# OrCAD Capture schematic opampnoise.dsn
size A
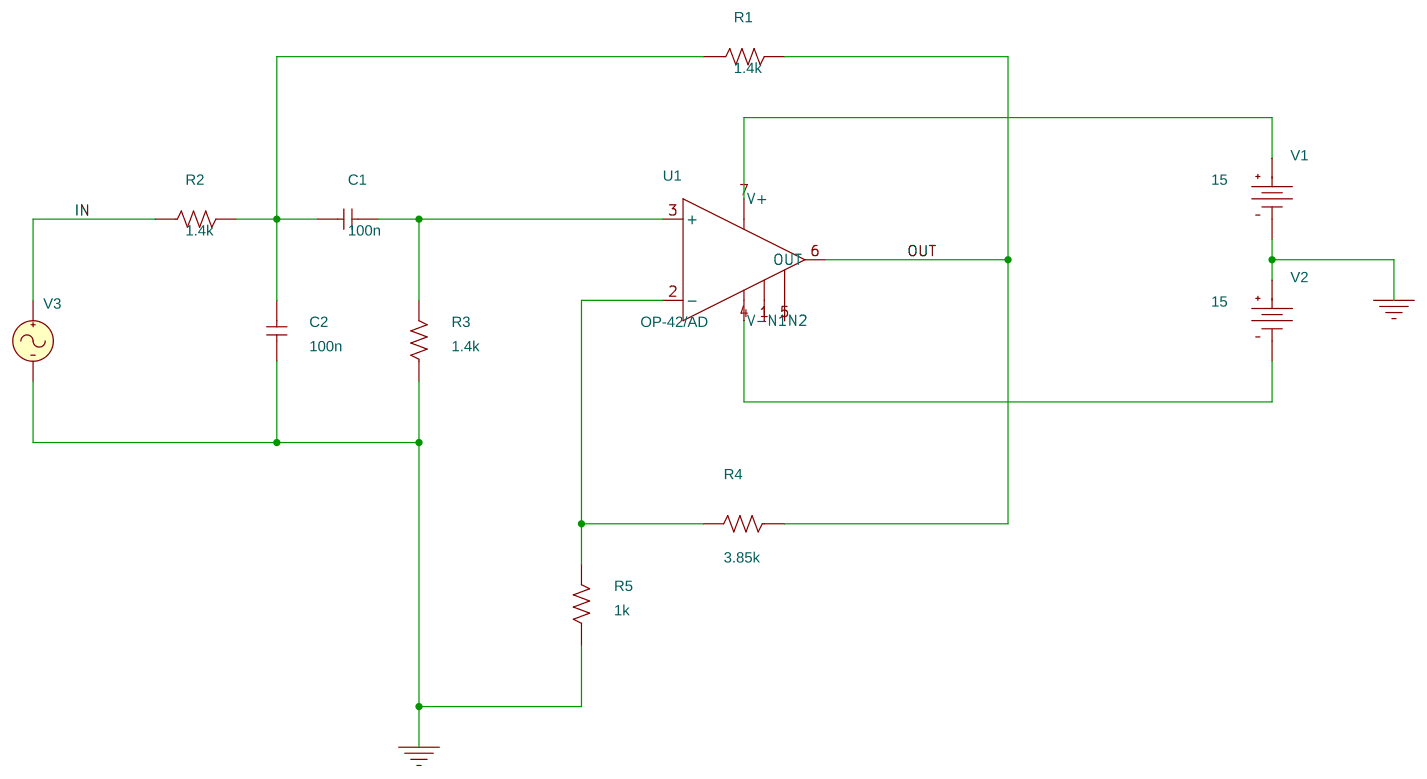
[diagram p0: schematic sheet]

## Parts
C1  100n  [RAD/CK05]
C2  100n  [RAD/CK05]
R1  1.4k  [AX/RC05]
R2  1.4k  [AX/RC05]
R3  1.4k  [AX/RC05]
R4  3.85k  [AX/RC05]
R5  1k  [AX/RC05]
U1  OP-42/AD  [DIP.100/8/W.300/L.425]
V1  VDC
V2  VDC
V3  VAC

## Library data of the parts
C1 C2 = C
R1-R5 = R
U1 = OP-42_AD
V1 V2 = VDC: DC: 15
V3 = VAC

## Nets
0: C2.1 R3.1 R5.1 V1.1(-) V2.0(+) V3.2(-)
IN: R2.1 V3.1(+)
OUT: R1.2 R4.1 U1.6(OUT)
N00643: C1.1 C2.2 R1.1 R2.2
N00707: C1.2 R3.2 U1.3(+)
N00737: R4.2 R5.2 U1.2(-)
N00929: U1.7(V+) V1.0(+)
N00938: U1.4(V-) V2.1(-)

Not connected (* = marked no-connect by the designer): U1 1(N1) 5(N2)
